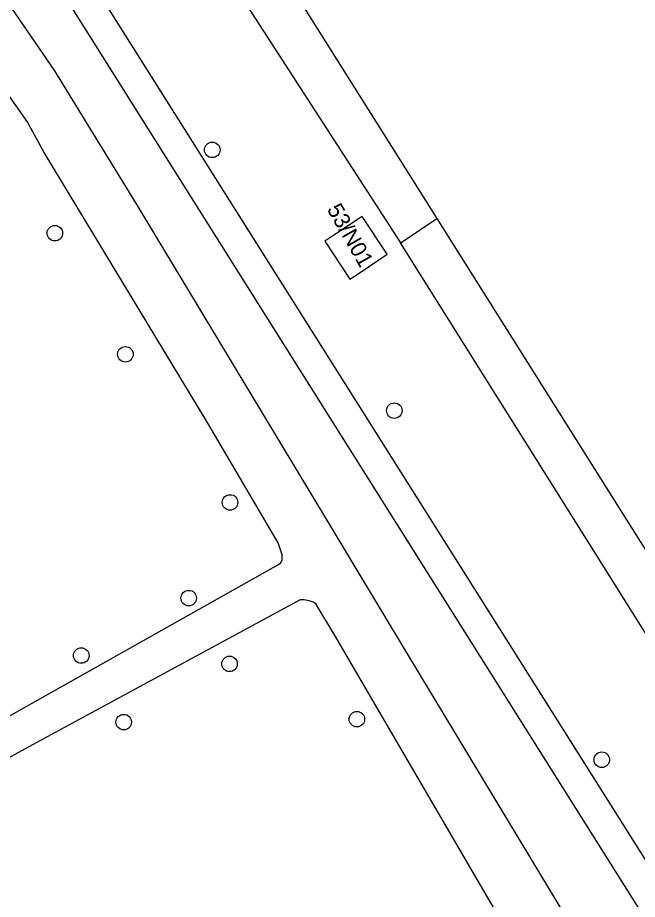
# Model space of a CAD drawing. Extents: x 163010 to 163853, y 382793 to 383982.
# Drawn here: x 163447.8 to 163486.8, y 383155.2 to 383210.8 of the extents above; entities that cross this region are included whole.
import ezdxf

# ---------------------------------------------------------------- set-up
doc = ezdxf.new("R2010")
doc.units = 0
for name, color, linetype in [('IMGEO_Boom', 7, 'Continuous'), ('IMGEO_Groenvoorziening', 7, 'Continuous'), ('IMGEO_Hek', 7, 'Continuous'), ('IMGEO_Pand', 7, 'Continuous'), ('IMGEO_Pand_nummerreeks', 7, 'Continuous'), ('IMGEO_Voetpad_gesloten', 7, 'Continuous'), ('IMGEO_Voetpad_open', 7, 'Continuous')]:
    doc.layers.add(name, color=color, linetype=linetype)

msp = doc.modelspace()

# ---------------------------------------------------------------- linework, layer by layer
at = {"layer": 'IMGEO_Boom'}
for centre in [(163460.06, 383202.449), (163450.153, 383197.198), (163454.595, 383189.572), (163471.519, 383186.023), (163461.179, 383180.239), (163458.578, 383174.213), (163451.816, 383170.594), (163461.147, 383170.069), (163454.487, 383166.399), (163469.165, 383166.587), (163484.58, 383164.031)]:
    msp.add_circle(centre, 0.489, dxfattribs=at)
at = {"layer": 'IMGEO_Groenvoorziening'}
for points in [[(163448.47, 383219.382), (163509.255, 383122.906)], [(163507.75, 383121.545), (163447.879, 383216.74)]]:
    msp.add_lwpolyline(points, dxfattribs=at)
at = {"layer": 'IMGEO_Hek'}
msp.add_lwpolyline([(163507.75, 383121.545), (163447.879, 383216.74)], dxfattribs=at)
at = {"layer": 'IMGEO_Pand'}
msp.add_lwpolyline([(163469.303, 383194.691), (163471.077, 383195.874), (163469.489, 383198.257), (163467.774, 383197.114), (163467.138, 383196.69), (163468.727, 383194.307), (163469.303, 383194.691)], dxfattribs=at)
at = {"layer": 'IMGEO_Voetpad_gesloten'}
for points in [[(163447.383, 383211.442), (163450.141, 383207.424), (163455.403, 383198.833), (163467.222, 383179.175), (163472.26, 383170.797), (163483.359, 383152.387), (163490.316, 383140.745), (163499.163, 383126.105), (163501.638, 383121.66), (163502.242, 383120.576), (163502.94, 383119.643), (163503.374, 383118.482), (163504.195, 383116.02), (163505.064, 383113.32), (163505.821, 383110.267), (163505.821, 383108.743), (163505.121, 383106.668), (163504.622, 383105.102)], [(163436.843, 383160.924), (163461.736, 383174.925), (163464.237, 383176.329), (163464.383, 383176.44), (163464.47, 383176.622), (163464.47, 383176.942), (163464.202, 383177.685), (163459.781, 383185.239), (163449.488, 383202.291), (163448.402, 383204.232), (163447.17, 383206.003)], [(163471.916, 383196.595), (163472.144, 383196.747), (163474.207, 383198.128)], [(163474.207, 383198.128), (163517.084, 383129.951)], [(163514.914, 383128.02), (163471.916, 383196.595)], [(163451.396, 383122.218), (163451.825, 383121.883), (163452.254, 383121.883), (163452.581, 383121.964), (163456.809, 383124.222), (163462.695, 383127.539), (163471.93, 383132.379), (163483.666, 383138.745), (163485.097, 383139.493), (163485.467, 383139.954), (163485.669, 383140.216), (163485.75, 383140.487), (163485.75, 383140.868), (163485.559, 383141.271), (163485.083, 383142.159), (163474.719, 383159.954), (163467.824, 383171.793), (163466.577, 383173.855), (163466.412, 383173.962), (163466.155, 383174.049), (163465.856, 383174.114), (163465.599, 383174.114), (163449.669, 383165.471), (163433.25, 383156.513)]]:
    msp.add_lwpolyline(points, dxfattribs=at)
at = {"layer": 'IMGEO_Voetpad_open'}
for points in [[(163458.131, 383217.924), (163471.916, 383196.595)], [(163462.133, 383217.32), (163474.207, 383198.128)]]:
    msp.add_lwpolyline(points, dxfattribs=at)

# ---------------------------------------------------------------- texts
at = {"layer": 'IMGEO_Pand_nummerreeks'}
msp.add_text('53/N01', height=1, rotation=299.7449, dxfattribs=at).set_placement((163467.252, 383198.708))

doc.saveas('drawing.dxf')
